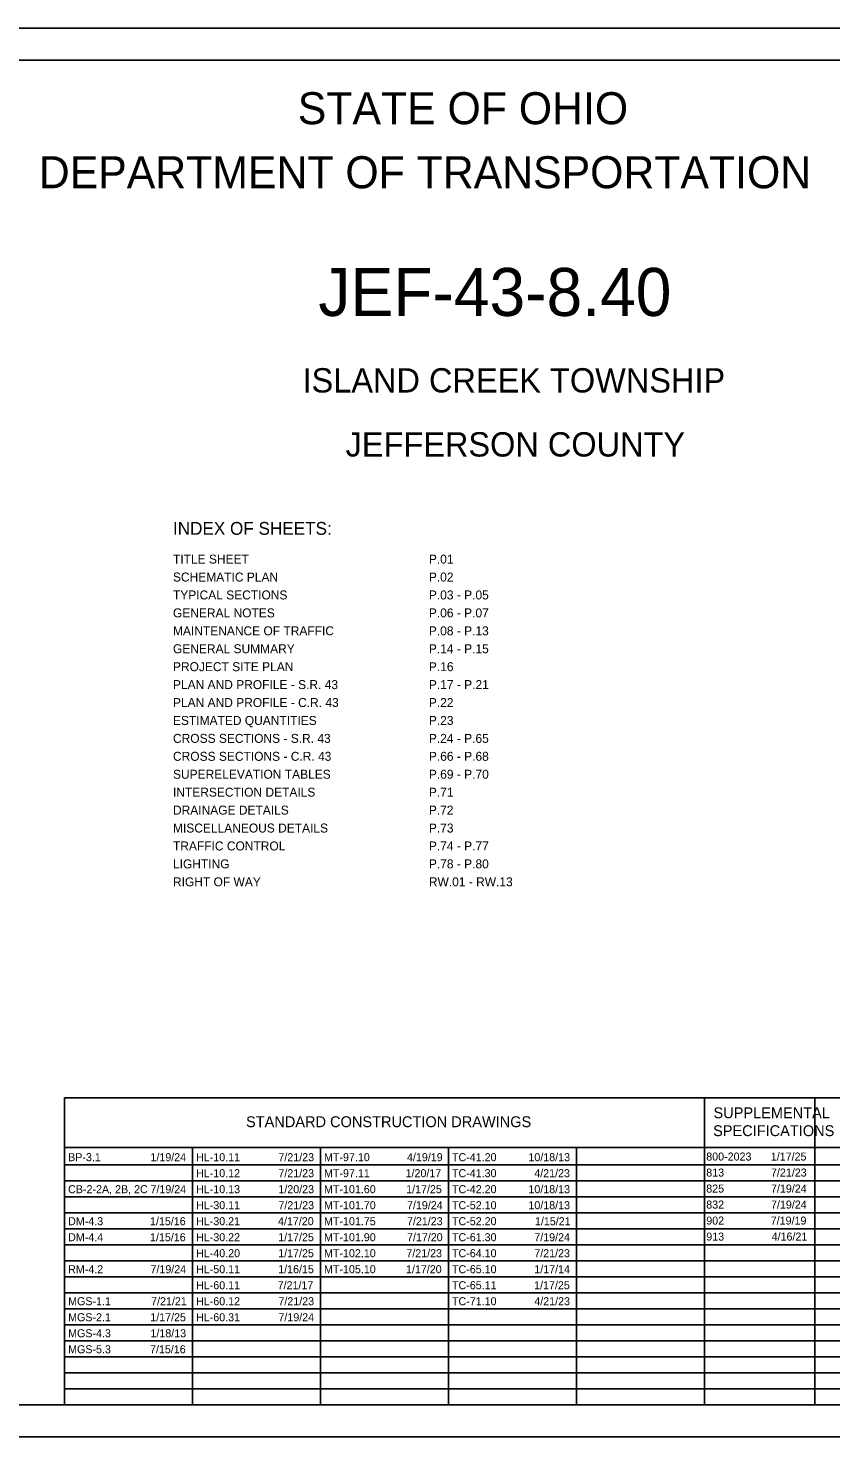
# Model space of a CAD drawing. Extents: x 0 to 34, y 0 to 22.
# Drawn here: x 9.58 to 22.13, y 0 to 22 of the extents above; entities that cross this region are included whole.
import ezdxf

# ---------------------------------------------------------------- set-up
doc = ezdxf.new("R2010")
doc.units = 0
for name, color, linetype in [('SH_Border', 7, 'Continuous'), ('SH_Cut_Line', 7, 'Continuous'), ('SH_Data', 7, 'Continuous'), ('SH_Text', 7, 'Continuous')]:
    doc.layers.add(name, color=color, linetype=linetype)

msp = doc.modelspace()

# ---------------------------------------------------------------- linework, layer by layer
at = {"layer": 'SH_Border'}
msp.add_lwpolyline([(1.5, 21.5), (33.5, 21.5), (33.5, 0.5), (1.5, 0.5)], close=True, dxfattribs=at)
at = {"layer": 'SH_Cut_Line'}
msp.add_lwpolyline([(0, 0), (34, 0), (34, 22), (0, 22)], close=True, dxfattribs=at)
at = {"layer": 'SH_Data'}
for p, q in [((10.15, 5.292), (23.6, 5.292)), ((10.15, 0.5), (10.15, 5.292)), ((20.15, 0.5), (20.15, 5.292)), ((21.875, 0.5), (21.875, 5.292)), ((10.15, 4.521), (23.6, 4.521)), ((12.15, 0.5), (12.15, 4.521)), ((14.15, 0.5), (14.15, 4.521)), ((16.15, 0.5), (16.15, 4.521)), ((18.15, 0.5), (18.15, 4.521)), ((10.15, 4.25), (23.6, 4.25)), ((10.15, 4), (23.6, 4)), ((10.15, 3.75), (23.6, 3.75)), ((10.15, 3.5), (23.6, 3.5)), ((10.15, 3.25), (23.6, 3.25)), ((10.15, 3), (23.6, 3)), ((10.15, 2.75), (23.6, 2.75)), ((10.15, 2.5), (23.6, 2.5)), ((10.15, 2.25), (23.6, 2.25)), ((10.15, 2), (23.6, 2)), ((10.15, 1.75), (23.6, 1.75)), ((10.15, 1.5), (23.6, 1.5)), ((10.15, 1.25), (23.6, 1.25)), ((10.15, 1), (23.6, 1)), ((10.15, 0.75), (23.6, 0.75))]:
    msp.add_line(p, q, dxfattribs=at)

# ---------------------------------------------------------------- texts
at = {"layer": 'SH_Text'}
for s, height, p in [('STATE OF OHIO', 0.5, (13.795, 20.5)), ('DEPARTMENT OF TRANSPORTATION', 0.5, (9.747, 19.5)), ('JEF-43-8.40', 0.75, (14.117, 17.505)), ('ISLAND CREEK TOWNSHIP', 0.38, (13.869, 16.31)), ('JEFFERSON COUNTY', 0.38, (14.542, 15.31)), ('INDEX OF SHEETS:', 0.2, (11.844, 14.088)), ('TITLE SHEET', 0.14, (11.844, 13.638)), ('P.01', 0.14, (15.844, 13.638)), ('SCHEMATIC PLAN', 0.14, (11.844, 13.358)), ('P.02', 0.14, (15.844, 13.358)), ('TYPICAL SECTIONS', 0.14, (11.844, 13.078)), ('P.03 - P.05', 0.14, (15.844, 13.078)), ('GENERAL NOTES', 0.14, (11.844, 12.798)), ('P.06 - P.07', 0.14, (15.844, 12.798)), ('MAINTENANCE OF TRAFFIC', 0.14, (11.844, 12.518)), ('P.08 - P.13', 0.14, (15.844, 12.518)), ('GENERAL SUMMARY', 0.14, (11.844, 12.238)), ('P.14 - P.15', 0.14, (15.844, 12.238)), ('PROJECT SITE PLAN', 0.14, (11.844, 11.958)), ('P.16', 0.14, (15.844, 11.958)), ('PLAN AND PROFILE - S.R. 43', 0.14, (11.844, 11.678)), ('P.17 - P.21', 0.14, (15.844, 11.678)), ('PLAN AND PROFILE - C.R. 43', 0.14, (11.844, 11.398)), ('P.22', 0.14, (15.844, 11.398)), ('ESTIMATED QUANTITIES', 0.14, (11.844, 11.118)), ('P.23', 0.14, (15.844, 11.118)), ('CROSS SECTIONS - S.R. 43', 0.14, (11.844, 10.838)), ('P.24 - P.65', 0.14, (15.844, 10.838)), ('CROSS SECTIONS - C.R. 43', 0.14, (11.844, 10.558)), ('P.66 - P.68', 0.14, (15.844, 10.558)), ('SUPERELEVATION TABLES', 0.14, (11.844, 10.278)), ('P.69 - P.70', 0.14, (15.844, 10.278)), ('INTERSECTION DETAILS', 0.14, (11.844, 9.998)), ('P.71', 0.14, (15.844, 9.998)), ('DRAINAGE DETAILS', 0.14, (11.844, 9.718)), ('P.72', 0.14, (15.844, 9.718)), ('MISCELLANEOUS DETAILS', 0.14, (11.844, 9.438)), ('P.73', 0.14, (15.844, 9.438)), ('TRAFFIC CONTROL', 0.14, (11.844, 9.158)), ('P.74 - P.77', 0.14, (15.844, 9.158)), ('LIGHTING', 0.14, (11.844, 8.878)), ('P.78 - P.80', 0.14, (15.844, 8.878)), ('RIGHT OF WAY', 0.14, (11.844, 8.598)), ('RW.01 - RW.13', 0.14, (15.844, 8.598)), ('SUPPLEMENTAL', 0.17, (20.293, 4.976)), ('STANDARD CONSTRUCTION DRAWINGS', 0.17, (12.986, 4.836)), ('SPECIFICATIONS', 0.17, (20.287, 4.696)), ('BP-3.1', 0.125, (10.205, 4.305)), ('1/19/24', 0.125, (11.492, 4.305)), ('HL-10.11', 0.125, (12.205, 4.305)), ('7/21/23', 0.125, (13.492, 4.305)), ('MT-97.10', 0.125, (14.205, 4.305)), ('4/19/19', 0.125, (15.502, 4.305)), ('TC-41.20', 0.125, (16.205, 4.305)), ('10/18/13', 0.125, (17.4, 4.305)), ('800-2023', 0.125, (20.18, 4.315)), ('1/17/25', 0.125, (21.189, 4.315)), ('HL-10.12', 0.125, (12.205, 4.055)), ('7/21/23', 0.125, (13.492, 4.055)), ('MT-97.11', 0.125, (14.205, 4.055)), ('1/20/17', 0.125, (15.48, 4.055)), ('TC-41.30', 0.125, (16.205, 4.055)), ('4/21/23', 0.125, (17.492, 4.055)), ('813', 0.125, (20.18, 4.065)), ('7/21/23', 0.125, (21.192, 4.065)), ('CB-2-2A, 2B, 2C', 0.125, (10.205, 3.805)), ('7/19/24', 0.125, (11.492, 3.805)), ('HL-10.13', 0.125, (12.205, 3.805)), ('1/20/23', 0.125, (13.492, 3.805)), ('MT-101.60', 0.125, (14.205, 3.805)), ('1/17/25', 0.125, (15.489, 3.805)), ('TC-42.20', 0.125, (16.205, 3.805)), ('10/18/13', 0.125, (17.4, 3.805)), ('825', 0.125, (20.18, 3.815)), ('7/19/24', 0.125, (21.192, 3.815)), ('HL-30.11', 0.125, (12.205, 3.555)), ('7/21/23', 0.125, (13.492, 3.555)), ('MT-101.70', 0.125, (14.205, 3.555)), ('7/19/24', 0.125, (15.502, 3.555)), ('TC-52.10', 0.125, (16.205, 3.555)), ('10/18/13', 0.125, (17.4, 3.555)), ('832', 0.125, (20.18, 3.565)), ('7/19/24', 0.125, (21.192, 3.565)), ('DM-4.3', 0.125, (10.205, 3.305)), ('1/15/16', 0.125, (11.485, 3.305)), ('HL-30.21', 0.125, (12.205, 3.305)), ('4/17/20', 0.125, (13.486, 3.305)), ('MT-101.75', 0.125, (14.205, 3.305)), ('7/21/23', 0.125, (15.502, 3.305)), ('TC-52.20', 0.125, (16.205, 3.305)), ('1/15/21', 0.125, (17.502, 3.305)), ('902', 0.125, (20.18, 3.315)), ('7/19/19', 0.125, (21.188, 3.315)), ('DM-4.4', 0.125, (10.205, 3.055)), ('1/15/16', 0.125, (11.485, 3.055)), ('HL-30.22', 0.125, (12.205, 3.055)), ('1/17/25', 0.125, (13.489, 3.055)), ('MT-101.90', 0.125, (14.205, 3.055)), ('7/17/20', 0.125, (15.502, 3.055)), ('TC-61.30', 0.125, (16.205, 3.055)), ('7/19/24', 0.125, (17.492, 3.055)), ('913', 0.125, (20.18, 3.065)), ('4/16/21', 0.125, (21.202, 3.065)), ('HL-40.20', 0.125, (12.205, 2.805)), ('1/17/25', 0.125, (13.489, 2.805)), ('MT-102.10', 0.125, (14.205, 2.805)), ('7/21/23', 0.125, (15.492, 2.805)), ('TC-64.10', 0.125, (16.205, 2.805)), ('7/21/23', 0.125, (17.492, 2.805)), ('RM-4.2', 0.125, (10.205, 2.555)), ('7/19/24', 0.125, (11.492, 2.555)), ('HL-50.11', 0.125, (12.205, 2.555)), ('1/16/15', 0.125, (13.489, 2.555)), ('MT-105.10', 0.125, (14.205, 2.555)), ('1/17/20', 0.125, (15.486, 2.555)), ('TC-65.10', 0.125, (16.205, 2.555)), ('1/17/14', 0.125, (17.492, 2.555)), ('HL-60.11', 0.125, (12.205, 2.305)), ('7/21/17', 0.125, (13.48, 2.305)), ('TC-65.11', 0.125, (16.205, 2.305)), ('1/17/25', 0.125, (17.489, 2.305)), ('MGS-1.1', 0.125, (10.205, 2.055)), ('7/21/21', 0.125, (11.502, 2.055)), ('HL-60.12', 0.125, (12.205, 2.055)), ('7/21/23', 0.125, (13.492, 2.055)), ('TC-71.10', 0.125, (16.205, 2.055)), ('4/21/23', 0.125, (17.492, 2.055)), ('MGS-2.1', 0.125, (10.205, 1.805)), ('1/17/25', 0.125, (11.489, 1.805)), ('HL-60.31', 0.125, (12.205, 1.805)), ('7/19/24', 0.125, (13.492, 1.805)), ('MGS-4.3', 0.125, (10.205, 1.555)), ('1/18/13', 0.125, (11.492, 1.555)), ('MGS-5.3', 0.125, (10.205, 1.305)), ('7/15/16', 0.125, (11.485, 1.305))]:
    msp.add_text(s, height=height, dxfattribs=at).set_placement(p)

doc.saveas('drawing.dxf')
